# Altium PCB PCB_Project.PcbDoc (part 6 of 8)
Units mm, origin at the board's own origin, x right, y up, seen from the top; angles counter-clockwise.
Board outline 250 x 200 mm, 6 copper layers (Top Shielding/Sig, Sig 1, PWR, GND, Sig 4, Bottom Shielding/Sig), stack 1.568 mm thick; 736 components, 420 nets, 1929 pads, 2185 vias.
Unrouted connection lines stored in the file: 47.
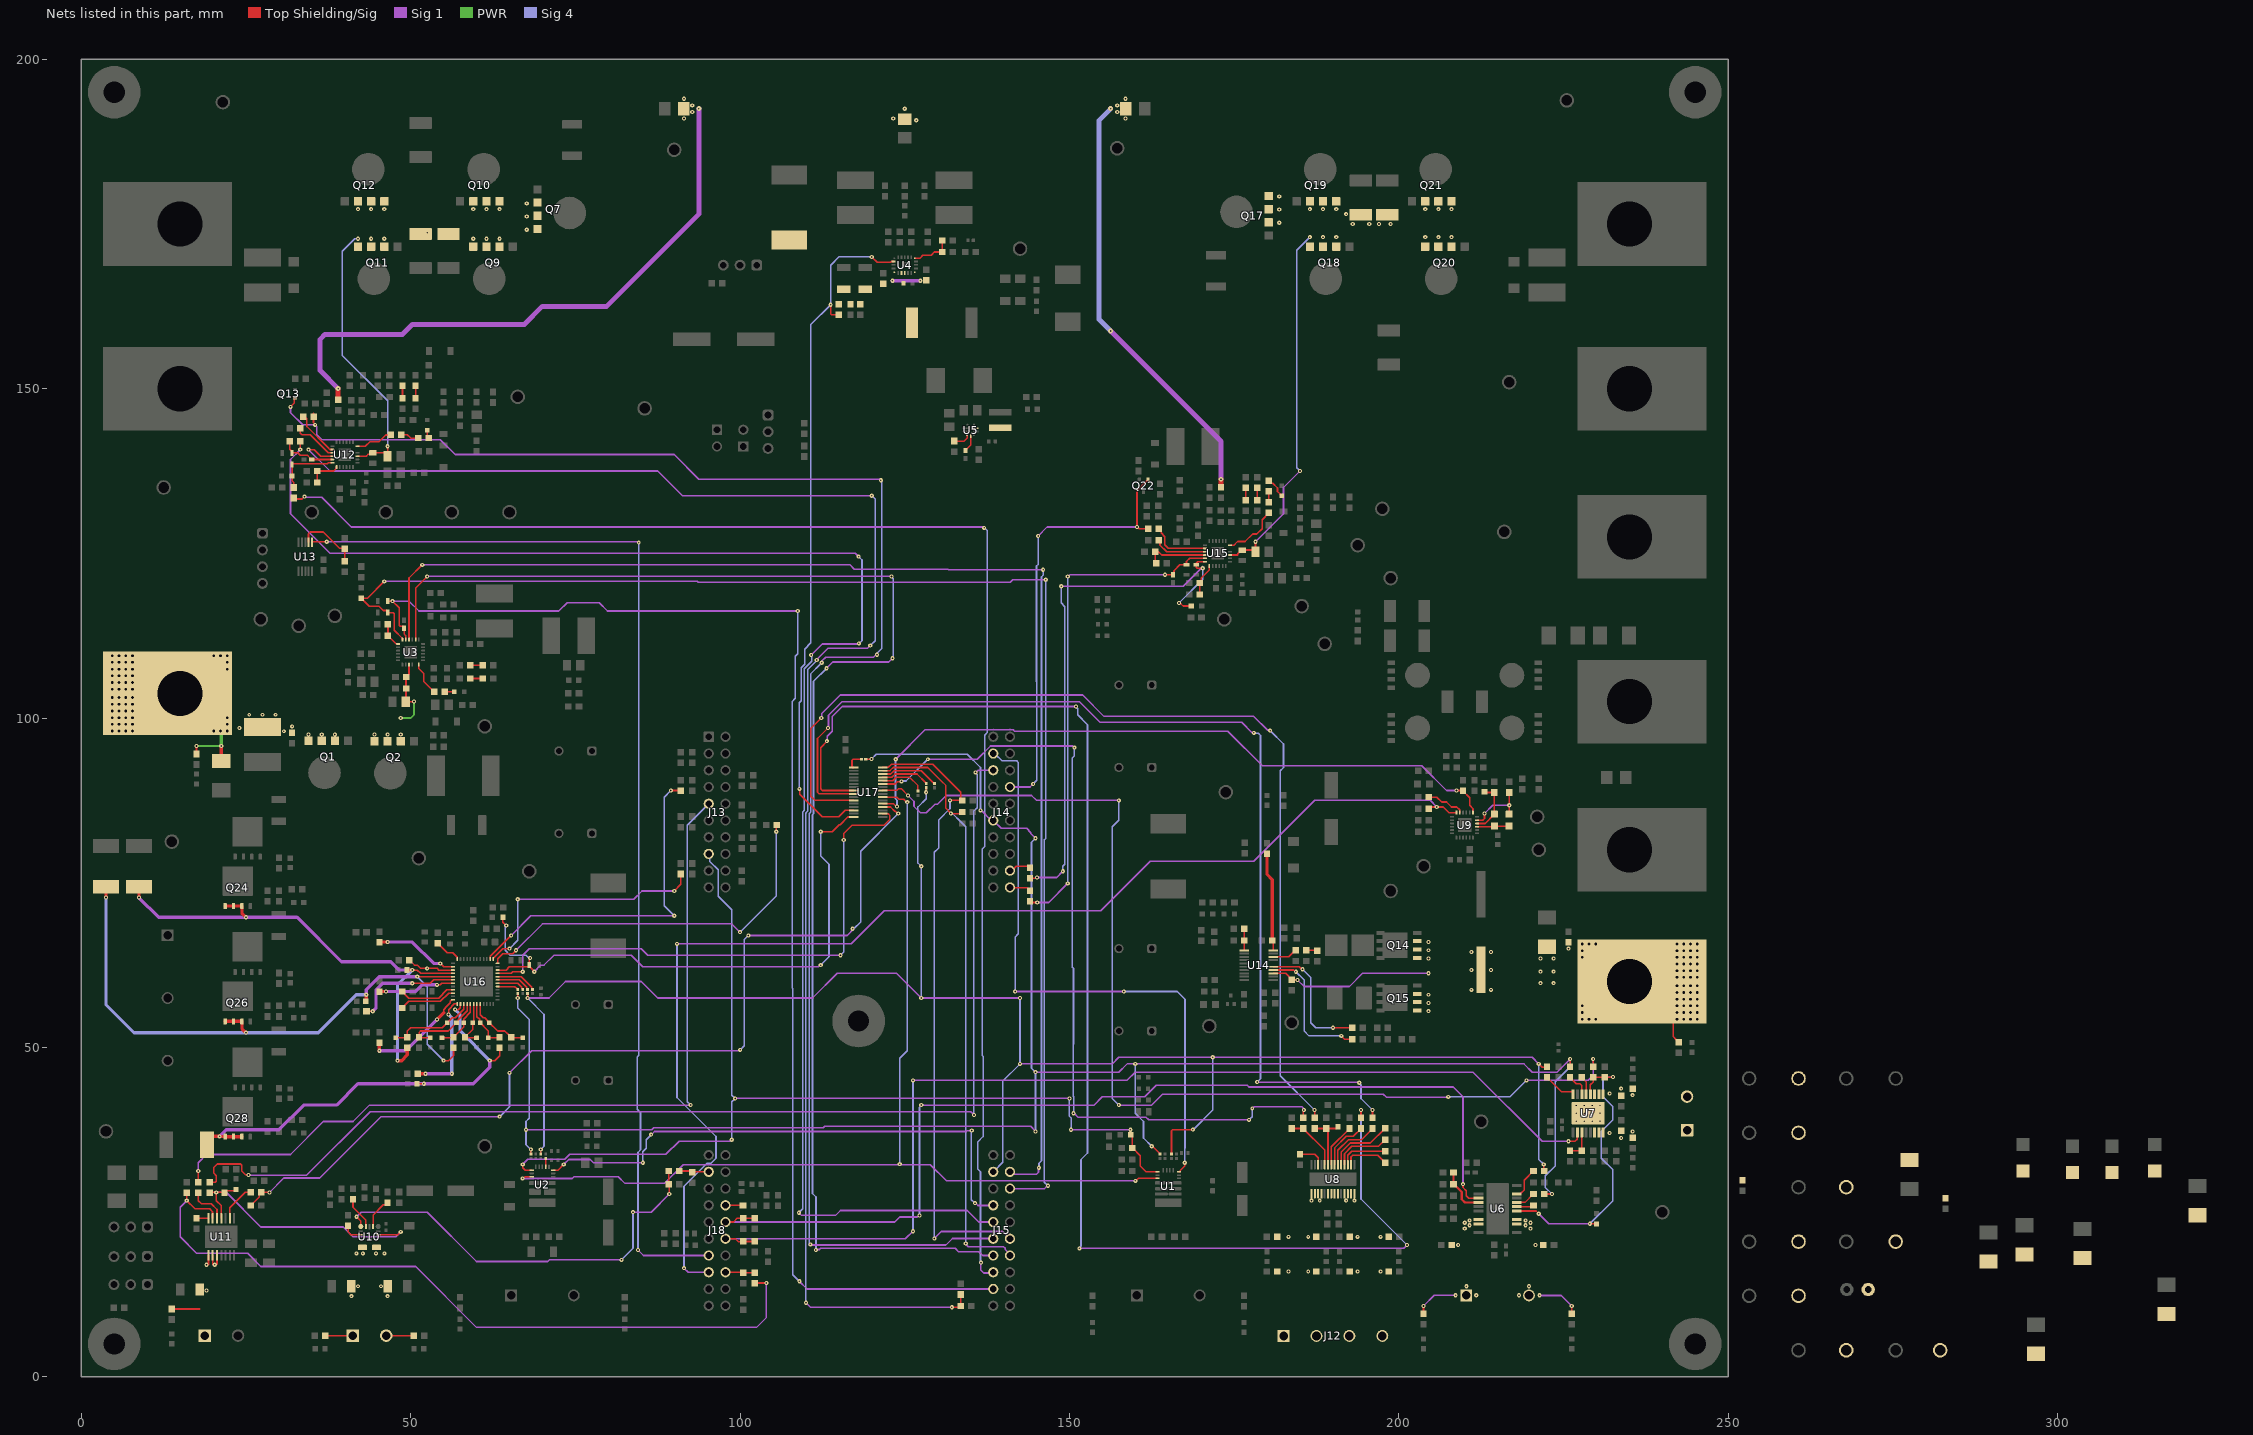
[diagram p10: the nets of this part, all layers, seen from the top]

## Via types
v1: diameter 0.635, hole 0.254, Top Shielding/Sig to Bottom Shielding/Sig, tented both sides, 778 vias
v2: diameter 0.6, hole 0.254, Top Shielding/Sig to Bottom Shielding/Sig, tented both sides, 726 vias
v3: diameter 0.813, hole 0.406, Top Shielding/Sig to Bottom Shielding/Sig, 522 vias
v4: diameter 0.5, hole 0.2, Top Shielding/Sig to Bottom Shielding/Sig, tented both sides, 95 vias
v5: diameter 0.5, hole 0.2, Top Shielding/Sig to Bottom Shielding/Sig, 39 vias
v6: diameter 0.635, hole 0.254, Top Shielding/Sig to Bottom Shielding/Sig, 10 vias
v7: diameter 0.63, hole 0.33, Top Shielding/Sig to Bottom Shielding/Sig, tented both sides, 6 vias
v8: diameter 0.75, hole 0.254, Top Shielding/Sig to Bottom Shielding/Sig, tented both sides, 6 vias
v9: diameter 0.5, hole 0.2, Top Shielding/Sig to Bottom Shielding/Sig, tented top, 3 vias

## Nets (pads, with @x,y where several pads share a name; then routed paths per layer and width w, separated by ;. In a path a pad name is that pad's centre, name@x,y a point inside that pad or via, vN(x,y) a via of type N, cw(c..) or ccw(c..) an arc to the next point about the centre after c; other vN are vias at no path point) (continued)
NetR20_2: R20.2 U2.12 | length 1.3
  Top Shielding/Sig w0.25: U2.12@70.5,31.875 R20.2@70.5,33.17
NetR28_1: R28.1 R31.2 | length 1.9
  Top Shielding/Sig w0.25: R31.2@59.05,108 R28.1@60.95,108
NetR29_1: R29.1 R32.2 | length 1.9
  Top Shielding/Sig w0.25: R32.2@59.05,106 R29.1@60.95,106
NetR37_2: R37.2 RNTC_1.1 | length 1.4
  Top Shielding/Sig w0.25: R37.2@55.175,104 RNTC_1.1@56.6,104
NetR60_2: R60.2 U5.7 | length 2.7
  Top Shielding/Sig w0.25: R60.2@132.5,142.05 132.55,142 134,142 134.463,142.463 U5.7@134.463,142.963
NetR90_1: R90.1 U8.2 | length 6.9
  Top Shielding/Sig w0.25: U8.2@192.75,32.2 192.75,33.375 193,33.625 196.8,33.625 197.925,32.5 R90.1@197.95,32.5
NetR91_1: R91.1 U8.3 | length 7.4
  Top Shielding/Sig w0.25: U8.3@192.25,32.2 192.25,33.625 192.875,34.25 R91.1@197.95,34.25
NetR92_1: R92.1 U8.4 | length 8.8
  Top Shielding/Sig w0.25: U8.4@191.75,32.2 191.75,33.875 192.875,35 196.925,35 197.925,36 R92.1@197.95,36
NetR93_1: R93.1 U8.5 | length 10.1
  Top Shielding/Sig w0.25: U8.5@191.25,32.2 191.25,34.125 192.625,35.5 195.675,35.5 197.925,37.75 R93.1@197.95,37.75
NetR94_1: R94.1 U8.8 | length 6.6
  Top Shielding/Sig w0.25: U8.8@189.75,32.2 189.75,34.925 192.5,37.675 R94.1@192.5,37.7
NetR95_1: R95.1 U8.7 | length 7.8
  Top Shielding/Sig w0.25: U8.7@190.25,32.2 190.25,34.73 192.02,36.5 193.075,36.5 194.25,37.675 R95.1@194.25,37.7
NetR96_1: R96.1 U8.6 | length 8.8
  Top Shielding/Sig w0.25: U8.6@190.75,32.2 190.75,34.375 192.375,36 194.325,36 196,37.675 R96.1@196,37.7
NetR98_1: R98.1 R100.1 U8.10 | length 8.6
  Top Shielding/Sig w0.25: R98.1@183.75,37.7 R100.1@185.5,37.7 185.5,37.675 188.75,34.425 U8.10@188.75,32.2
NetR102_2: R102.2 U8.12 | length 4
  Top Shielding/Sig w0.2: R102.2@185,33.8 185.05,33.75 187.25,33.75 187.75,33.25 U8.12@187.75,32.2
NetR127_2: R127.2 U9.11 | length 5.9
  Top Shielding/Sig w0.25: R127.2@204.55,88 205.75,88 206.5,87.25 207.25,87.25 208,86.5 208.814,86.5 209.241,86.072 209.241,85.878 209.25,85.869 U9.11@209.25,85.65
NetR131_2: R131.2 U10.9 | length 4.5
  Top Shielding/Sig w0.25: R131.2@41.25,26.5 41.25,25.75 43.2,23.8 U10.9@43.2,22.825
NetR132_2: R132.2 U10.7 | length 4.7
  Top Shielding/Sig w0.25: U10.7@44.3,22.825 44.3,24.55 45.847,26.097 46.15,26.097 46.5,26.447 R132.2@46.5,26.45
NetR133_1: R133.1 R135.2 U10.10 | length 63.6
  Top Shielding/Sig w0.25: v1(41.796,24.296) 42.424,23.667 U10.10@42.424,22.825 ; R133.1@89.2,31.25 R135.2@89.2,29.25 89.25,29.2 v1(89.25,27.75)
  Sig 1 w0.25: v1(41.796,24.296) 42.5,25 52.5,25 60,17.5 70.823,17.5 71.073,17.75 v1(82,17.75) ; v1(83.75,25) 86.5,25 v1(89.25,27.75)
  Sig 4 w0.25: v1(82,17.75) 83.75,19.5 v1(83.75,25)
NetR137_2: R137.2 U10.12 | length 3
  Top Shielding/Sig w0.25: R137.2@40.5,22.95 40.5,22 40.925,21.575 U10.12@42.4,21.575
NetR143_2: R143.2 U11.2 | length 5.7
  Top Shielding/Sig w0.25: U11.2@22.55,24.05 22.55,25.654 24.896,28 R143.2@25.7,28
NetR144_2: R144.2 U11.5 | length 6
  Top Shielding/Sig w0.25: R144.2@17.75,27.95 17.75,26.75 18.25,26.25 19.75,26.25 20.6,25.4 U11.5@20.6,24.05
NetR145_2: R145.2 U11.7 | length 1.9
  Top Shielding/Sig w0.25: R145.2@17.5,23.8 17.75,24.05 U11.7@19.3,24.05
NetR156_1: R156.1 R181.2 U12.4 | length 248.3
  Top Shielding/Sig w0.25: v1(34.5,140.75) 35.341,140.75 36.341,139.75 U12.4@38.1,139.75 ; v1(132.155,10.558) 133.125,10.558 133.25,10.683 R181.2@133.25,10.75 ; R181.2@133.5,10.75 R156.1@133.5,12.5
  Sig 1 w0.25: v1(34.5,140.75) 37.75,137.5 87.5,137.5 91.25,133.75 v1(120,133.75) ; v1(110,11.25) 110.692,10.558 v1(132.155,10.558) ; v1@111.639,108.889 113.357,110.608 119.358,110.608 v1(119.75,111)
  Sig 4 w0.25: v1(110,11.25) 109.95,11.3 109.95,85.564 110.25,85.864 110.25,107.335 111.564,108.649 111.564,108.661 v1@111.5,108.725 ; v1(119.75,111) 120.5,111.75 120.5,133.25 v1(120,133.75)
  other v1: 111.645,108.819
NetR163_1: R163.1 R167.2 | length 1.9
  Top Shielding/Sig w0.25: R167.2@50.75,148.55 R163.1@50.75,150.45
NetR164_1: R164.1 R168.2 | length 1.9
  Top Shielding/Sig w0.25: R168.2@48.75,148.55 R164.1@48.75,150.45
NetR176_2: R176.2 U12.3 | length 6.7
  Top Shielding/Sig w0.25: R176.2@33.25,144 33.25,143.25 33.5,143 34.75,143 37.5,140.25 U12.3@38,140.25
NetR178_2: R178.2 U12.2 | length 6.9
  Top Shielding/Sig w0.25: R178.2@33.95,145.75 34.25,145.45 34.25,144.25 37.475,141.025 37.475,141.02 37.735,140.76 U12.2@38.09,140.76
NetR179_1: R179.1 R180.1 | length 2.8
  Top Shielding/Sig w0.25: R179.1@48.55,143 49.5,143 50,142.5 R180.1@51.15,142.5
NetR179_2: R179.2 U12.18 | length 5.8
  Top Shielding/Sig w0.25: U12.18@41.9,141.25 43.114,141.25 43.814,141.95 45.2,141.95 46.221,142.971 46.971,142.971 R179.2@47,143
NetR180_2: R180.2 RNTC_2.1 | length 1.3
  Top Shielding/Sig w0.25: RNTC_2.1@52.5,143.7 52.5,142.75 R180.2@52.75,142.5
NetR196_1: R196.1 R201.1 | length 1.7
  Top Shielding/Sig w0.212: R201.1@185.925,64.75 187.55,64.75 R196.1@187.625,64.675
NetR200_1: R200.1 R203.2 U14.1 | length 3.3
  Top Shielding/Sig w0.25: U14.1@176.55,64.75 R203.2@176.55,66.25 R200.1@176.55,68
NetR201_2: R201.2 U14.18 | length 3.8
  Top Shielding/Sig w0.25: U14.18@180.925,63.725 U14.18@180.95,63.75 183.3,63.75 184.3,64.75 R201.2@184.325,64.75
NetR205_2: R205.2 U14.15 | length 19.9
  Top Shielding/Sig w0.25: U14.15@180.95,62.25 184.896,62.25 185.271,61.875 v1(185.375,61.875) ; v1(190,53) R205.2@192.95,53
  Sig 4 w0.25: v1(185.375,61.875) 186.625,60.625 186.625,53.75 187.375,53 v1(190,53)
NetR206_2: R206.2 U14.14 | length 20.9
  Top Shielding/Sig w0.25: U14.14@180.95,61.75 184.021,61.75 184.271,61.5 v1(184.375,61.5) ; v1(191.25,51.75) 191.75,51.25 R206.2@192.95,51.25
  Sig 4 w0.25: v1(184.375,61.5) 185.625,60.25 185.625,52.5 186.375,51.75 191.125,51.75 v1@191.25,51.625
NetR224_1: R224.1 R228.2 | length 1.9
  Top Shielding/Sig w0.25: R228.2@176.75,133.05 R224.1@176.75,134.95
NetR225_1: R225.1 R229.2 | length 1.9
  Top Shielding/Sig w0.25: R229.2@178.5,133.05 R225.1@178.5,134.95
NetR237_2: R237.2 U15.3 | length 7.9
  Top Shielding/Sig w0.25: R237.2@163.75,127 163.75,126.25 164.75,125.25 U15.3@170.5,125.25
NetR239_2: R239.2 U15.2 | length 9.2
  Top Shielding/Sig w0.2: R239.2@163.5,128.75 163.75,128.5 163.775,128.5 163.9,128.375 163.9,128.1 164.476,127.524 164.476,126.274 165,125.75 U15.2@170.6,125.75
NetR240_1: R240.1 R241.1 | length 1.5
  Top Shielding/Sig w0.25: R240.1@180.25,132.75 R241.1@180.25,134.25 ; R241.1@180.25,134.375 R241.1@180.25,134.4
NetR240_2: R240.2 U15.18 | length 8.6
  Top Shielding/Sig w0.25: U15.18@174.5,126.25 174.973,126.25 175.523,126.8 176.664,126.8 177.814,127.95 178.45,127.95 179.25,128.75 179.25,130.125 180.25,131.125 R240.2@180.25,131.15
NetR241_2: R241.2 RNTC_3.1 | length 3.3
  Top Shielding/Sig w0.25: R241.2@180.25,136 180.25,135.975 180.6,135.625 180.875,135.625 181.575,134.925 181.575,134.4 182.025,133.95 182.025,133.925 182.225,133.725 RNTC_3.1@182.25,133.725
NetR242_2: R242.2 R297.1 U15.4 | length 9.6
  Top Shielding/Sig w0.25: R297.1@163.2,123.5 163,123.7 R242.2@163,125.25 163.5,125.25 164,124.75 U15.4@170.6,124.75
NetR256_2: R256.2 U16.19 | length 5.2
  Top Shielding/Sig w0.2: U16.19@63.212,60.25 66.503,60.25 67.64,59.113 67.64,58.94 R256.2@67.75,58.83
NetR258_2: R258.2 U16.18 | length 4.3
  Top Shielding/Sig w0.2: U16.18@63.212,59.75 66.253,59.75 66.89,59.113 66.89,58.94 R258.2@67,58.83
NetR259_2: R259.2 U16.17 | length 3.2
  Top Shielding/Sig w0.2: U16.17@63.212,59.25 65.83,59.25 66.12,58.96 66.14,58.96 66.25,58.85 R259.2@66.25,58.83
NetR260_2: R260.2 U16.20 | length 6.2
  Top Shielding/Sig w0.2: U16.20@63.212,60.75 66.753,60.75 68.39,59.113 68.39,58.94 R260.2@68.5,58.83
NetR263_1: R263.1 U16.36 | length 4.1
  Top Shielding/Sig w0.2: R263.1@54.125,65.825 54.125,65.8 54.5,65.425 54.525,65.425 55.575,64.375 56.375,64.375 57.042,63.708 57.042,63.42 U16.36@57.062,63.4
NetR264_2: R264.2 U16.38 | length 12.7
  Top Shielding/Sig w0.2: v1(54.5,62.75) 55,62.25 U16.38@56.412,62.25
  Top Shielding/Sig w0.25: R264.2@45.25,65.95 R264.2@45.3,66
  Top Shielding/Sig w0.5: R264.2@45.3,66 v1(46.5,66)
  Sig 1 w0.5: v1(46.5,66) 50.25,66 53.5,62.75 v1(54.5,62.75)
NetR268_2: R268.2 U16.39 | length 7.2
  Top Shielding/Sig w0.2: v1(52.5,62) 54,62 54.25,61.75 U16.39@56.412,61.75
  Top Shielding/Sig w0.25: R268.2@49.8,63.25 49.825,63.25 50.575,62.5 51,62.5 51.5,62 v1(52.5,62)
NetR269_1: R269.1 U16.45 | length 8.7
  Top Shielding/Sig w0.2: R269.1@48.7,58.5 48.725,58.5 49.1,58.125 49.1,58.1 49.7,57.5 54.25,57.5 55.5,58.75 U16.45@56.412,58.75
NetR271_2: R271.2 U16.43 | length 11.7
  Top Shielding/Sig w0.2: v1(54,59.5) 54.013,59.487 54.487,59.487 54.75,59.75 U16.43@56.412,59.75
  Top Shielding/Sig w0.5: R271.2@45.25,58.45 45.3,58.5 v1(46.25,58.5)
  Sig 1 w0.5: v1(46.25,58.5) 50.75,58.5 51.75,59.5 v1(54,59.5)
NetR272_2: R272.2 U16.42 | length 16.7
  Top Shielding/Sig w0.2: v1(50.25,59.75) 53,59.75 53.5,60.25 U16.42@56.412,60.25
  Top Shielding/Sig w0.25: R272.2@43.3,55.5 v1(44.25,55.5)
  Sig 1 w0.5: v1(44.25,55.5) 44.75,56 44.75,58.75 45.75,59.75 v1(50.25,59.75)
NetR274_1: R274.1 U16.46 | length 8.7
  Top Shielding/Sig w0.2: R274.1@48.7,56 48.725,56 49.1,56.375 49.1,56.4 49.7,57 54.5,57 55.75,58.25 U16.46@56.412,58.25
NetR275_2: R275.2 U16.48 | length 16
  Top Shielding/Sig w0.2: 55,55.25 55,55.75 55.5,56.25 56,56.75 56,57.018 56.232,57.25 U16.48@56.412,57.25
  Top Shielding/Sig w0.5: v1(45.25,49.5) R275.2@45.25,50.7 ; v1(54,54.25) 55,55.25
  Sig 1 w0.5: v1(45.25,49.5) 49.25,49.5 v1(54,54.25)
NetR276_2: R276.2 U16.1 | length 16.8
  Top Shielding/Sig w0.2: v1(55.75,55) 55.75,55.75 56.6,56.6 U16.1@57.062,56.6
  Top Shielding/Sig w0.5: R276.2@51.05,46 v1(52.25,46)
  Sig 1 w0.5: v1(52.25,46) v1(56.25,46)
  Sig 4 w0.5: v1(55.75,55) 56.25,54.5 v1(56.25,46)
NetR278_2: R278.2 U16.26 | length 52.5
  Top Shielding/Sig w0.2: U16.26@62.062,63.4 U16.26@62.062,63.4 62.063,63.813 v1(65.25,67)
  Top Shielding/Sig w0.25: v1(89.5,89) 90.95,89 R278.2@91,88.95
  Sig 1 w0.25: v1(65.25,67) 68.25,70 v1(90,70)
  Sig 4 w0.25: v1(89.5,89) 88.5,88 88.5,71.5 v1(90,70)
NetR279_2: R279.2 U16.25 | length 38.5
  Top Shielding/Sig w0.2: U16.25@62.562,63.4 62.562,63.58 62.582,63.6 62.6,63.6 64,65 v1(65,65)
  Top Shielding/Sig w0.25: v1(90,73.75) 91,74.75 R279.2@91,76.325
  Sig 1 w0.25: v1(66.25,72.5) 83.875,72.5 85.125,73.75 v1(90,73.75)
  Sig 4 w0.25: v1(65,65) 66.25,66.25 v1(66.25,72.5)
NetR280_2: R280.2 U16.24 | length 58.8
  Top Shielding/Sig w0.2: U16.24@63.212,62.75 63.212,63.462 64,64.25 65.5,64.25 v1(66,64.75)
  Top Shielding/Sig w0.25: v1(105.5,82.75) 105.5,83.7 R280.2@105.55,83.75
  Sig 1 w0.25: v1(66,64.75) 70,68.75 98.75,68.75 v1(100,67.5)
  Sig 4 w0.25: v1(100,67.5) 105.5,73 v1(105.5,82.75)
NetR293_2: R293.2 U17.29 | length 7.4
  Top Shielding/Sig w0.25: U17.29@121.65,91 121.675,91.025 123.048,91.025 123.523,91.5 126.85,91.5 128.165,90.185 R293.2@128.259,90.091
NetR294_2: R294.2 U17.30 | length 8.9
  Top Shielding/Sig w0.25: U17.30@121.65,91.5 122.886,91.5 123.386,92 127.5,92 129.315,90.185 129.415,90.185 R294.2@129.517,90.083
NetR295_2: R295.2 U17.1 | length 2.8
  Top Shielding/Sig w0.25: U17.1@117.25,92.5 117.025,92.5 117,92.525 117,93.604 117.146,93.75 R295.2@118.42,93.75
NetR296_2: R296.2 U17.28 | length 6.9
  Top Shielding/Sig w0.25: U17.28@121.65,90.5 123.159,90.5 123.694,91.035 125.715,91.035 127,89.75 R296.2@127,89
NetR302_1: R302.1 R303.2 U13.2 | length 9.9
  Top Shielding/Sig w0.25: U13.2@34.5,126.7 34.5,128 34.75,128.25 36.75,128.25 39.25,125.75 40,125.75 R302.1@40,125.7 R303.2@40,123.8
NetR306_2: R306.2 TP44.1 U7.17
  other v4: 226.95,38.8 228.15,38.8 230.55,38.8 226.95,40 228.15,40 230.55,40 226.95,41.2 228.15,41.2 230.55,41.2
  other v9: 229.35,38.8 229.35,40 229.35,41.2
NetR307_2: R307.2 TP46.1 U8.20 U8.21 U8.22 U8.23
nFAULT_48V_efuse_1: J14.38 R147.1 | length 179.5
  Top Shielding/Sig w0.25: R147.1@19.5,29.55 20.35,29.55 20.496,29.696 20.496,30.537 20.108,30.926 20.108,31.766 20.641,32.3 24.185,32.3 24.375,32.11 24.375,31.234 24.91,30.699 25.298,30.699 v1(25.372,30.625)
  Sig 1 w0.25: v1(25.372,30.625) 34.239,30.625 43.864,40.25 135,40.25 v1(135.5,39.75) ; v2(135.75,91.75) 135.845,91.75 136.17,92.075 138.325,92.075 J14.38@138.415,92.165
  Sig 4 w0.25: v1(135.5,39.75) 135.5,85.884 136,86.384 136,91.429 135.75,91.679 v2(135.75,91.75)
nFAULT_48V_efuse_5: D28.1 R146.1 R147.2 U10.4 U11.4 | length 43.2
  Top Shielding/Sig w0.25: R147.2@19.5,27.95 19.7,27.95 19.75,28 v1(20.5,28) ; U11.4@21.25,24.05 21.25,26 20.5,26.75 v1(20.5,28) ; D28.1@23.5,28.45 23.3,28.25 22.05,28.25 R146.1@21.75,27.95 21.7,28 v1(20.5,28) ; U10.4@45.1,21.575 48.075,21.575 v1(48.5,22)
  Sig 1 w0.25: v1(20.5,28) 22,28 27.25,22.75 39.75,22.75 41.25,21.25 47.75,21.25 v1(48.5,22)
nFAULT_1212_1_2: D37.1 R184.1 R185.1 U12.6 | length 9.7
  Top Shielding/Sig w0.25: R185.1@32.25,135 32.25,135.75 32,136 D37.1@32,136.75 R184.1@32,138.5 32.125,138.625 37.375,138.625 37.5,138.75 U12.6@38,138.75
nFAULT_1212_2_3: D46.1 R245.1 R246.1 U15.6 | length 83.9
  Top Shielding/Sig w0.2: R245.1@169.25,123.25 169.25,122.867 169.367,122.75 v1(170.25,122.75)
  Top Shielding/Sig w0.25: R246.1@144,75.7 v1@144.95,75.7 ; v2@166.75,117.5 167.25,117 D46.1@168.5,117 ; R245.1@169.25,123.25 169.25,123.5 169.5,123.75 U15.6@170.6,123.75
  Sig 1 w0.2: v1(148.75,120) 167.25,120 v1@170.25,123
  Sig 1 w0.25: v1@145,75.75 145.051,75.801 v1(145.076,75.801) 148.051,75.801 v1(149,76.75)
  Sig 4 w0.2: v1(148.75,120) 148.75,117.5 149.325,116.925 149.325,77.803 149,77.478 v1(149,76.75)
  Sig 4 w0.25: v2(166.643,117.464) 170.25,121.07 v1(170.25,122.75) v1@170.25,123
nFAULT_1214: D9.1 J15.58 R40.1 U3.6 | length 214.1
  Top Shielding/Sig w0.25: v1(46,120.75) 43.45,118.2 D9.1@42.5,118.2 43.725,116.975 45.185,116.975 45.835,116.325 46.375,116.325 46.5,116.2 R40.1@46.5,116 47.354,116 47.5,115.854 47.5,113.325 48.75,112.075 U3.6@48.75,111.9
  Sig 1 w0.25: v1(46,120.75) 93.489,120.75 93.631,120.607 141.016,120.607 141.409,121 v1(146.393,121) ; J15.58@141,28.75 141.175,28.575 146.221,28.575 146.646,29 v1(146.75,29)
  Sig 4 w0.25: J15.58@141,28.5 J15.58@141.072,28.572 ; v1(146.393,121) 146.393,81.709 146.2,81.516 146.2,29.55 v1(146.75,29)
nFAULT_DRV82xx_1: D3.1 J13.8 R4.1 U1.1 U2.1 | length 154.3
  Top Shielding/Sig w0.2: v1(67,32.25) 67,31.75 67.375,31.375 U2.1@68.375,31.375
  Top Shielding/Sig w0.25: v1(159.25,37.5) 159.25,36.8 D3.1@159.3,36.75 159.55,36.5 R4.1@159.55,34.75 159.575,34.75 160.75,33.575 160.75,32 161.625,31.125 U1.1@163.375,31.125
  Sig 1 w0.2: v1(67,32.25) 67.75,33 73.399,33 74.149,33.75 88.75,33.75 90.75,35.75 98.415,35.75 98.665,36 v1(98.75,36) ; v1(99.25,42.25) v1(150,42.25) ; v1(150.25,37.5) v1(159.25,37.5)
  Sig 4 w0.25: J13.8@95.25,79.375 95.416,79.209 95.416,78.225 96.69,76.951 96.69,72.944 98.75,70.884 98.75,42.75 v1(99.25,42.25) 98.75,41.75 v1(98.75,36) ; v1(150,42.25) 149.965,42.215 149.965,39.586 150.25,39.301 v1(150.25,37.5)
nFAULT_DRV8363: D50.1 R262.1 U16.22 U17.16 | length 89.3
  Top Shielding/Sig w0.2: U16.22@63.212,61.75 64.5,61.75 65,62.25 67.85,62.25 R262.1@67.95,62.35 ; R262.1@68,62.5 68,62.3 68.75,61.55 v1(68.75,61.5)
  Top Shielding/Sig w0.25: D50.1@64,69.75 64,69 v1(64.5,68.5) ; R262.1@68,62.5 v1@68,63.5 ; v1(112.25,82.75) 113.99,82.75 115.04,83.8 115.186,83.8 116.361,84.975 117.225,84.975 U17.16@117.25,85
  Sig 1 w0.25: v1(68.75,61.5) 69.75,62.5 70.25,62.5 71.75,64 83.5,64 85.25,62.25 111.911,62.25 112.161,62.5 v1(112.25,62.5)
  Sig 4 w0.25: v1(64.5,68.5) 64.5,68.396 64.357,68.253 64.357,64.734 65.091,64 67.521,64 v1@68,63.521 ; v1(112.25,62.5) 113.5,63.75 113.5,77.823 112.25,79.073 v1(112.25,82.75)
  other v1: 68.13,63.568
nFAULT_LM74900_1: J18.48 R125.1 U9.12 | length 187.4
  Top Shielding/Sig w0.25: R125.1@204.55,86.25 204.8,86.5 v1(205.75,86.5) 206.75,86.5 207.6,85.65 U9.12@208.75,85.65
  Sig 1 w0.25: v2@90.5,65.75 116.866,65.75 121.866,70.75 154.75,70.75 162.25,78.25 178,78.25 187.25,87.5 204.75,87.5 v1(205.75,86.5) ; v2(91.5,16.5) 92.125,15.875 95.125,15.875 J18.48@95.25,15.75
  Sig 4 w0.25: v2(90.437,65.726) 90.437,42.404 96.35,36.491 96.35,33.199 95.536,32.385 94.964,32.385 91.5,28.921 v2(91.5,16.5)
nFAULT_TPS4HC120_1: R99.2 U17.11 | length 153.4
  Top Shielding/Sig w0.25: v1(112.339,100) 110.75,98.411 110.75,88.114 111.364,87.5 U17.11@117.25,87.5 ; R99.2@187.25,39.3 v1@187.25,40.5
  Sig 1 w0.25: v1(112.339,100) 112.412,100.074 112.412,100.685 115.227,103.5 152,103.5 155.25,100.25 178,100.25 180.094,98.156 180.401,98.156 v2(180.468,98.089)
  Sig 4 w0.25: v2@180.5,98 180.557,98 182.5,96.057 182.5,92.5 182,92 182,45.705 v1(187.2,40.505)
nFLT_LM686x5_1: R49.1 U4.8 U17.14 | length 105.6
  Top Shielding/Sig w0.25: v1(109,89.25) 109.074,89.176 109.074,88.426 112.5,85 114.967,85 115.967,86 U17.14@117.25,86 ; v6(113.75,162.75) 113.75,161.346 113.896,161.2 R49.1@115,161.2 R49.1@115.05,161.25 ; v1(120,170) 120.832,169.168 122.813,169.168 122.945,169.3 U4.8@123.3,169.3
  Sig 4 w0.25: v1(109,89.25) 109,102.321 109.3,102.621 109.3,107.658 109.8,108.158 109.8,110.465 110.75,111.415 110.75,159.75 v6(113.75,162.75) 113.75,168.75 115,170 v1(120,170)
nFLT_TPS2HCS10/05_1: R84.1 U17.25 | length 164.3
  Top Shielding/Sig w0.25: U17.25@121.65,89 121.675,89.025 122.344,89.025 123.836,89.025 124.061,89.25 124.5,89.25 v1(125.5,88.25) ; R84.1@229.5,47.05 v1(229.5,48.25)
  Sig 1 w0.25: v1(125.5,88.25) 126.412,87.338 126.412,86.588 127.393,85.607 128.266,85.607 129.587,86.929 129.974,86.929 131.295,88.25 144.25,88.25 145,87.5 v1(157.5,87.5) ; v1(157.5,41.25) 162.5,41.25 164.125,42.875 180.876,42.875 180.893,42.892 197.644,42.892 198.071,42.465 207.465,42.465 v1(207.5,42.5) ; v1(219.375,45) 228.75,45 229.5,45.75 v1(229.5,48.25)
  Sig 4 w0.25: v1(157.5,41.25) 156.573,42.177 156.5,42.25 156.5,52.275 cw(c157.5,52.5) 156.5,52.725 156.5,64.775 cw(c157.5,65) 156.5,65.225 156.5,83.5 157.5,84.5 v1(157.5,87.5) ; v1(207.5,42.5) 216.875,42.5 v1(219.375,45)
nFLT_TPS2HCS10/05_4: D14.1 R82.1 R84.2 U6.13 U7.12 | length 45.6
  Top Shielding/Sig w0.25: U6.13@217.9,25.175 220.825,25.175 v1(221.25,24.75) ; v1(229,23.25) 229.95,23.25 D14.1@230,23.2 ; U7.12@229.075,42.9 229.075,44.325 229.5,44.75 R84.2@229.5,45.45 R82.1@231.25,45.45 231.3,45.5 v1(232.5,45.5)
  Sig 1 w0.25: v1(221.25,24.75) 222.75,23.25 v1(229,23.25)
  Sig 4 w0.25: v1(229,23.25) 232.5,26.75 232.5,31.45 230.75,33.2 230.75,37.25 232.5,39 232.5,41 231,42.5 231,45 231.5,45.5 v1(232.5,45.5)
nFLT_TPS4HC120_9: D19.1 R97.1 R99.1 U8.9 | length 9.2
  Top Shielding/Sig w0.25: R99.1@187.25,37.7 R97.1@189,37.7 ; U8.9@189.25,32.2 189.25,37.45 R97.1@189,37.7 ; D19.1@190.75,37.95 190.5,37.7 R97.1@189,37.7
nFLT_TPS1212_input1_1: J15.73 R185.2 | length 222.6
  Top Shielding/Sig w0.25: R185.2@32.25,133.5 32.5,133.25 33.5,133.25 33.858,133.608 v2(33.895,133.608)
  Sig 1 w0.25: v2@34,133.5 36.5,133.5 41,129 v2@137,129 ; v2@136.54,17.114 136.54,16.21 137,15.75 J15.73@138.5,15.75
  Sig 4 w0.25: v2@136.5,17.25 136.5,31.119 136.108,31.511 136.108,35.699 136.892,36.484 136.892,48.671 136.75,48.813 136.75,80.125 137.125,80.5 137.125,97.406 137.5,97.781 137.5,128.5 v2@137,129
  other v2: 136.569,17.322 137.051,128.878
nFLT_TPS1212_input2_1: J14.12 R246.2 | length 3.2
  Top Shielding/Sig w0.25: J14.12@140.97,76.835 141.266,76.835 141.931,77.5 R246.2@143.75,77.5 ; J14.12@141,76.75 J14.12@141.027,76.777 ; R246.2@144,77.3 R246.2@144.085,77.385
nINT_TXE8124_1: J15.55 R290.2 U17.32 | length 96.8
  Top Shielding/Sig w0.25: U17.32@121.65,92.5 121.663,92.513 122.513,92.513 123,93 129.25,93 133.5,88.75 R290.2@133.5,87.5 ; v2(131.875,87.5) R290.2@133.5,87.5 ; R290.2@133.7,87.5 R290.2@133.5,87.5
  Sig 1 w0.25: v1(129.5,21) 130.555,22.055 139.87,22.055 140.925,21 J15.55@141,21
  Sig 4 w0.25: v1(129.5,21) 129.5,79.636 130.143,80.279 130.143,84.526 131.875,86.259 v2(131.875,87.5)
nLPM_TPS4HC120_1: R100.2 U17.27 | length 125.5
  Top Shielding/Sig w0.25: U17.27@121.65,90 123.538,90 123.857,90.319 124.426,90.319 v1(124.5,90.393) ; R100.2@185.5,39.3 v1@185.5,40.5
  Sig 1 w0.25: v2(128.5,93.75) 136.009,93.75 138.009,95.75 150.5,95.75 v2(150.75,95.5) ; v1(150.607,40) 150.712,40 151.312,39.4 161.623,39.4 162.023,39 v2(177.25,39) ; v2(177.75,40.75) 177.835,40.75 178.071,40.987 185.297,40.987 185.513,40.77 185.513,40.578 v1(185.587,40.504)
  Sig 4 w0.25: v1(124.5,90.393) 124.55,90.442 125.192,90.442 v2(128.5,93.75) ; v1(150.607,40) 150.643,40.035 150.643,42.516 150.57,42.589 150.57,50.446 150.607,50.484 150.607,62.006 150.45,62.164 150.45,93.95 150.75,94.25 v2@150.75,95.25 ; v2(177.25,39) 177.75,39.5 v2(177.75,40.75)
nLPM_TPS1212_input1_1: J15.75 Q13.1 R178.1 | length 252.1
  Top Shielding/Sig w0.25: v2(31.75,147.25) 32.354,147.854 32.354,148.49 32.364,148.5 Q13.1@32.5,148.5 ; 35.25,146.25 35.25,144.854 35.5,144.604 v1(35.5,144.5)
  Sig 1 w0.25: v2(31.75,147.25) 31.75,146.366 33.616,144.5 v1(35.5,144.5) 35.75,144.25 35.75,143 36.5,142.25 54.5,142.25 56.75,140 90,140 93.75,136.25 v1@121.25,136.25 ; v2@110.544,20 131.25,20 132.25,21 J15.75@138.25,21 ; v1@112.253,108.247 112.327,108.321 112.327,108.577 113,109.25 120.25,109.25 120.635,109.635 v1@120.635,109.683
  Sig 4 w0.25: v2@110.5,20 110.5,20.118 110.5,85.477 110.708,85.685 110.708,106.701 v1@112.253,108.247 ; v1@120.635,109.683 121.5,110.548 121.5,135.911 121.25,136.161 v1@121.25,136.25
  other v1: 112.388,108.391 120.779,109.61 121.372,136.099
  other v2: 110.661,20.118
nLPM_TPS1212_input2_1: J14.17 Q22.1 R239.1 | length 66.5
  Top Shielding/Sig w0.25: Q22.1@161.75,136 160.25,134.5 v1(160.25,129) 160.354,129 160.604,128.75 R239.1@161.95,128.75
  Sig 1 w0.25: J14.17@140.97,89.535 144.01,89.535 144.475,90 v2(144.5,90) ; v1(145.25,127.643) 146.607,129 v1(160.25,129)
  Sig 4 w0.25: v2@144.666,90.166 145.05,90.55 145.05,105.471 145,105.521 145,123.073 145.25,123.323 v1(145.25,127.643)
nLPM_TPS1214_1: J15.74 U3.2 | length 220.7
  Top Shielding/Sig w0.25: U3.2@50.75,111.9 50.75,119.75 v1(52.5,121.5)
  Sig 1 w0.25: v1(52.5,121.5) v1(123,121.5) ; v2(111.5,19.25) 111.567,19.317 112.067,19.317 112.25,19.5 132.659,19.5 133.159,19 136.25,19 136.835,18.415 J15.74@138.43,18.415 ; v1@113.25,107.5 113.25,107.674 114.076,108.5 122.576,108.5 v1(123.145,109.069)
  Sig 4 w0.25: v2(111.5,19.25) 111.53,19.28 111.53,27.299 111,27.829 111,85.341 111.157,85.498 111.157,105.582 v1(113.145,107.569) ; v1(123,121.5) 123,121.411 123.25,121.161 v1@123.25,109.25
nSLEEP_DRV82xx_1: U1.3 U2.3 U17.23 | length 159.8
  Top Shielding/Sig w0.25: v2@67.25,30.25 67.375,30.375 U2.3@68.375,30.375 ; U17.23@121.65,88 123.795,88 124.123,87.672 124.848,87.672 125.25,87.27 v1@125.25,87.25 ; v2(160,29.75) 160.095,29.75 160.47,30.125 U1.3@163.375,30.125
  Sig 1 w0.25: v2(67,30.125) 67.018,30.107 74.516,30.107 74.801,30.392 81.491,30.392 82.526,29.358 88.5,29.358 91.357,32.215 128.875,32.215 131.34,29.75 v2(160,29.75)
  Sig 4 w0.25: v1@124.25,32.25 124.25,48.341 125.385,49.476 v1(125.385,87.239)
  other v1: 124.234,32.283
nSLEEP_DRV8363_1: U16.21 U17.18 | length 83.9
  Top Shielding/Sig w0.2: U16.21@63.212,61.25 65.25,61.25 65.5,61.5 v1(67,61.5)
  Top Shielding/Sig w0.25: v1(115.75,81.5) 115.766,81.516 115.766,82.516 117,83.75 121.864,83.75 122.75,84.636 122.75,85.206 122.481,85.475 121.675,85.475 U17.18@121.65,85.5
  Sig 1 w0.25: v1(67,61.5) 67,64 68,65 85,65 86,64 v1(115.25,64)
  Sig 4 w0.25: v1(115.25,64) 115.75,64.5 v1(115.75,81.5)
nSLEEP_LM74900_1: R124.1 U9.7 U17.21 | length 105.3
  Top Shielding/Sig w0.25: U17.21@121.65,87 123.304,87 123.725,86.579 v1(123.829,86.579) ; v1(208.75,89) R124.1@209.675,89 ; R124.1@209.75,88.95 209.75,88.925 210.75,87.925 210.75,86.75 211.25,86.25 U9.7@211.25,85.65
  Sig 1 w0.25: v1(123.625,93.744) 128.131,98.25 138.325,98.25 cw(c138.43,97.155) 138.535,98.25 140.865,98.25 cw(c140.97,97.155) 141.075,98.25 141.431,98.25 141.504,98.177 141.681,98 174.05,98 179.3,92.75 203.5,92.75 207.25,89 v1(208.75,89)
  Sig 4 w0.25: v1(123.625,93.744) 123.607,93.727 123.607,87.756 123.829,87.535 v1(123.829,86.579)
OUT1_TPS4HC120: C86.1 D55.1 J12.4 R105.2 U8.27 U8.28
  other v2: 197.25,16 197.25,21.25 193.25,26.75
OUT2_TPS4HC120: C89.1 D56.1 J12.3 R106.2 U8.25 U8.26
  other v2: 193.75,16 193.75,21.25 192,26.75
OUT3_TPS4HC120: C90.1 D57.1 J12.2 R107.2 U8.17 U8.18
  other v2: 186.25,16 186.25,21.25 188,26.75
OUT4_TPS4HC120: C91.1 D58.1 J12.1 R108.2 U8.15 U8.16
  other v2: 183.25,16 183.25,21.25 186.75,26.75
OV_11: R121.2 R122.2 U9.5 | length 9.5
  Top Shielding/Sig w0.25: U9.5@211.9,84.5 212.75,84.5 213,84.75 v1(213,85.5) ; R122.2@216.75,85.401 R121.2@216.75,88.7
  Sig 1 w0.25: v1(213,85.5) 214.25,86.75 v1(216.75,86.75)
PH/IN2_DRV8245_1: J14.39 U1.12 | length 92.2
  Top Shielding/Sig w0.25: U1.12@166.625,31.125 166.825,31.125 166.825,31.325 167.5,32 v1(167.5,32.5)
  Sig 1 w0.25: v1(141.75,58.5) v2(158.25,58.5)
  Sig 4 w0.25: J14.39@138.5,94.5 138.75,94.5 139.75,93.5 142,93.5 142.25,93.25 142.25,67.25 141.75,66.75 v1(141.75,58.5) ; v2(158.25,58.5) 166.364,58.5 167.55,57.314 167.55,34.734 167.5,34.684 v1(167.5,32.5)
PH/IN2_DRV8263_1: J15.77 U2.10 | length 82
  Top Shielding/Sig w0.25: U2.10@71.625,31.375 72.375,31.375 v1(73.25,32.25)
  Sig 1 w0.25: v1(73.25,32.25) 74,33 77.25,33 77.75,32.5 v1(85.25,32.5) ; v2(86.5,36.75) 87,37.25 134.357,37.25 134.482,37.375 135.157,37.375 v1(135.175,37.393) ; v1(135.656,26.37) 135.76,26.37 136.13,26 J15.77@138.25,26
  Sig 4 w0.25: v1(85.25,32.5) 85.25,34.177 85.75,34.677 85.75,36 v2(86.5,36.75) ; v1(135.175,37.393) 135.107,37.325 135.107,26.893 v1@135.5,26.5
RESET_TXE8124_1: J15.54 R292.2 U17.31 | length 91.4
  Top Shielding/Sig w0.25: U17.31@121.65,92 121.675,92.025 122.775,92.025 123.25,92.5 128.5,92.5 130.5,90.5 131.25,89.75 131.25,86.321 132,85.571 v2(132,85.5) 133.325,85.5 133.5,85.675 R292.2@133.5,85.75
  Sig 1 w0.25: v6(134.25,20.25) 134.25,20.146 134.646,19.75 140,19.75 140.25,19.5 140.25,19.321 141,18.571 J15.54@141,18.25
  Sig 4 w0.25: v2(132,85.5) 132.067,85.433 132.317,85.433 133.408,84.342 134.25,83.5 v6(134.25,20.25)
SCLK_1: J15.79 R10.1 R13.1 R65.1 R83.1 R256.1 R293.1 | length 282.8
  Top Shielding/Sig w0.25: v1(67.75,57.5) R256.1@67.75,58.17 ; R13.1@69.75,33.83 v1(69.75,34.5) ; v1(128.25,88.75) R293.1@128.25,89.42 ; R10.1@165.5,33.83 165.5,37.354 165.672,37.526 v2(168.741,37.526) ; v1(221.25,47.5) 221.75,47 222.45,47 R83.1@222.5,47.05 ; v1(222,32.25) 222,31.3 R65.1@222.05,31.25
  Sig 1 w0.25: v1(67.75,57.5) 71,57.5 73.5,60 85,60 87.5,57.5 111,57.5 114.75,61.25 123.75,61.25 v1(127.5,57.5) v1(142.5,57.5) ; v1(142.5,47.5) 156.5,47.5 157.5,48.5 v1(171.75,48.5) 220.25,48.5 v1(221.25,47.5)
  Sig 4 w0.25: v1(67.75,57.5) 70.25,55 70.25,35 v1(69.75,34.5) ; v1(127.5,57.5) v1(127.5,77.5) 127,78 127,86.5 128.25,87.75 v1(128.25,88.75) ; J15.79@138.5,31.25 138.565,31.25 139.87,32.555 139.87,38.712 139.893,38.735 139.893,44.893 v1(142.5,47.5) v1(142.5,57.5) ; v2(168.741,37.526) 168.776,37.526 171.75,40.5 v1(171.75,48.5) ; v1(221.25,47.5) 221.25,33 v1(222,32.25)
SCLK_HCS05_4: R65.2 U6.17 | length 4.9
  Top Shielding/Sig w0.25: U6.17@217.9,27.775 218.425,27.775 219.016,28.366 219.016,29.841 220.425,31.25 R65.2@220.45,31.25
SCLK_HCS10_4: R83.2 U7.16 | length 5.2
  Top Shielding/Sig w0.25: R83.2@222.5,45.45 222.5,45.425 222.85,45.075 222.875,45.075 224.7,43.25 226.375,43.25 226.475,43.15 U7.16@226.475,42.9
SCP_TEST_TPS1214_1: J15.59 U3.4 | length 203.1
  Top Shielding/Sig w0.25: U3.4@49.75,111.9 49.75,121.25 v1(51.75,123.25)
  Sig 1 w0.25: v1(51.75,123.25) 116.679,123.25 117.337,122.593 131.57,122.593 131.663,122.5 v1(146,122.5) ; J15.59@140.97,31.115 141.322,31.115 141.687,30.75 145,30.75 145.308,31.058 145.308,31.7 v1(145.357,31.75)
  Sig 4 w0.25: v1(145.357,31.75) 145.375,31.767 145.375,32.442 145.75,32.818 145.75,121.409 146,121.659 v1(146,122.5)
SDI_HCS05_4: R67.2 U6.14 | length 2.6
  Top Shielding/Sig w0.25: U6.14@217.9,25.825 220.275,25.825 R67.2@220.45,26
SDI_HCS10_4: R86.2 U7.13 | length 2.8
  Top Shielding/Sig w0.25: R86.2@227.75,45.45 227.75,45.425 228.425,44.75 U7.13@228.425,42.9
SDO_1: J14.35 R11.1 R19.1 R68.1 R87.1 R259.1 R295.1 | length 306.8
  Top Shielding/Sig w0.25: v1(66.25,57.5) R259.1@66.25,58.17 ; R19.1@68.25,33.83 v1(68.25,34.5) ; R295.1@119.08,93.75 119.097,93.767 119.949,93.767 v1(119.966,93.784) ; v1(162.5,35) 162.6,35 163.75,33.85 R11.1@163.75,33.83 ; R68.1@222.05,27.75 v1(223.25,27.75) ; R87.1@226,47.05 v1(226,48.25)
  Sig 1 w0.25: v1(67.5,37.5) 86.614,37.5 86.914,37.8 112.633,37.8 112.868,38.035 144.111,38.035 144.858,37.288 v1(144.858,37.25) ; v2(136.5,86) 136.595,86 138.095,84.5 138.5,84.5 138.5,84.385 139.635,83.25 143.5,83.25 144.142,82.608 144.142,82.466 v1(144.858,81.75) ; v1(144.858,46.25) 157.5,46.25 158.75,47.5 v1(160,47.5) 219,47.5 220.25,46.25 224,46.25 v1(226,48.25)
  Sig 4 w0.25: v1(66.25,57.5) 66.25,56 68,54.25 68,39.25 67.5,38.75 v1(67.5,37.5) 67.5,35.25 v1(68.25,34.5) ; v1(119.966,93.784) 120.682,94.5 134.5,94.5 136.5,92.5 v2@136.5,86.25 ; v1(144.858,37.25) v1(144.858,46.25) ; v1(144.858,81.75) 144.25,81.142 144.25,46.857 v1(144.858,46.25) ; v1@144.929,46.321 v1(144.858,46.25) ; v1(160,47.5) 160,40 161.25,38.75 161.25,36.25 v1(162.5,35) ; v1(223.25,27.75) 222.25,28.75 222.25,30.5 223.75,32 223.75,44.8 226,47.05 v1(226,48.25)
SDO_HCS05_4: R68.2 U6.15 | length 3.1
  Top Shielding/Sig w0.25: U6.15@217.9,26.475 219.15,26.475 220.425,27.75 R68.2@220.45,27.75
SDO_HCS10_4: R87.2 U7.14 | length 3.6
  Top Shielding/Sig w0.25: R87.2@226,45.45 226,45.425 226.925,44.5 227.5,44.5 227.775,44.225 U7.14@227.775,42.9
SEL0_TPS4HC120_1: R95.2 U17.8 | length 212.5
  Top Shielding/Sig w0.25: v1(113.181,96.5) 113.181,96.431 112.25,95.5 112.25,89.25 112.5,89 U17.8@117.25,89 ; R95.2@194.25,39.3 v1(194.25,40.5)
  Sig 1 w0.25: v1(113.181,96.5) 113.25,96.569 113.25,97.25 114,98 114,100.25 115.5,101.75 v2(151,101.75) ; v2(151.5,19.5) 200.75,19.5 v1(201.25,20)
  Sig 4 w0.25: v2(151,101.75) 151,101.655 151.25,101.405 151.25,100.5 152.75,99 152.75,33.978 151.75,32.978 151.75,19.821 151.5,19.571 v2(151.5,19.5) ; v1(194.25,40.5) 194.25,27 v1(201.25,20)
SEL1_TPS4HC120_1: R96.2 U17.9 | length 161.1
  Top Shielding/Sig w0.25: v1(113.357,98.5) 111.75,96.893 111.75,88.75 111.975,88.525 117.225,88.525 U17.9@117.25,88.5 ; R96.2@196,39.3 v1(196,40.5)
  Sig 1 w0.25: v1(113.357,98.5) 113.431,98.574 113.431,100.431 115.5,102.5 151.5,102.5 154.65,99.35 176.15,99.35 177.683,97.817 177.933,97.817 v2(178,97.75) ; v2(178.5,44.75) 178.554,44.696 193.946,44.696 v1(194,44.643)
  Sig 4 w0.25: v2(178,97.75) 178.061,97.689 178.675,97.689 179,97.364 179,95.75 179,45.25 v2(178.5,44.75) ; v1(194,44.643) 194,44.554 194.25,44.304 194.25,42.25 v1(196,40.5)
SLA_10: Q24.1 Q24.2 Q24.3 R265.2 R281.2 R284.2 U16.40 | length 77
  Top Shielding/Sig w0.2: v1(50.25,61.75) 51,61.75 51.5,61.25 U16.40@56.412,61.25
  Top Shielding/Sig w0.5: v1(8.75,72.75) R284.2@8.75,74.4 ; Q24.1@21.845,71.455 Q24.2@23.115,71.455 Q24.3@24.385,71.455 24.385,70.365 v1(25,69.75) ; v1(48,48) 48.625,48 49.5,48.875 R281.2@49.5,49.95 ; R265.2@49.45,61.75 v1(50.25,61.75)
  Sig 1 w0.5: v1(8.75,72.75) 11.75,69.75 v1(25,69.75) 32.75,69.75 39.5,63 47,63 48.25,61.75 v1(50.25,61.75)
  Sig 4 w0.5: v1(48,48) 48,59.5 v1(50.25,61.75)
SLB_10: Q26.1 Q26.2 Q26.3 R270.2 R282.2 R285.2 U16.41 | length 99.2
  Top Shielding/Sig w0.2: v1(51,60.75) U16.41@56.412,60.75
  Top Shielding/Sig w0.25: v1(55,48) 55.75,48 56.5,48.75 R282.2@56.5,49.95
  Top Shielding/Sig w0.5: v1(3.75,72.75) R285.2@3.75,74.4 ; Q26.1@21.845,53.955 Q26.3@24.385,53.955 24.385,52.865 v1(25,52.25) ; R270.2@43.2,57 43.25,57.05 v1(43.25,58)
  Sig 1 w0.5: v1(43.25,58) 43.25,58.75 45.25,60.75 v1(51,60.75)
  Sig 4 w0.2: v1(51,60.75) 52.5,59.25 52.5,50.5 v1(55,48)
  Sig 4 w0.5: v1(3.75,72.75) 3.75,56.5 8,52.25 v1(25,52.25) 36,52.25 41.75,58 v1(43.25,58)
SLC_10: Q28.1 Q28.2 Q28.3 R277.2 R283.2 R286.2 U16.2 | length 67.9
  Top Shielding/Sig w0.2: v1(56.75,55.75) 57.25,55.75 57.562,56.062 U16.2@57.562,56.6
  Top Shielding/Sig w0.25: R277.2@50.95,44.5 v1(52,44.5) ; v1(62,48) 62.75,48 63.5,48.75 R283.2@63.5,49.95
  Top Shielding/Sig w0.5: R286.2@19.1,35.25 19.1,35.7 19.9,36.5 v1(21,36.5) 21.023,36.478 21.822,36.478 Q28.1@21.845,36.455 Q28.2@23.115,36.455 Q28.3@24.385,36.455
  Sig 1 w0.5: v1(21,36.5) 22,37.5 30,37.5 33.75,41.25 38.75,41.25 42,44.5 v1(52,44.5) 59.5,44.5 62,47 v1(62,48)
  Sig 4 w0.5: v1(56.75,55.75) 57.5,55 57.5,52.5 v1(62,48)
SNA_10: C193.1 C196.2 R287.1 U16.4 | length 12.3
  Top Shielding/Sig w0.2: C193.1@57.033,53.833 57.198,53.998 57.198,54.198 58.562,55.562 U16.4@58.562,56.6
  Top Shielding/Sig w0.25: C196.2@53,51.45 51.35,51.45 R287.1@51.25,51.55 51.279,51.579 51.279,52.279 51.5,52.5 55.7,52.5 C193.1@56.95,53.75 C193.1@57.033,53.833
SNB_10: C194.1 C197.2 R288.1 U16.6 | length 7.4
  Top Shielding/Sig w0.2: C194.1@59.562,53.862 U16.6@59.562,56.6
  Top Shielding/Sig w0.25: C194.1@59.562,53.862 C194.1@59.45,53.75 59.45,52.775 58.25,51.575 R288.1@58.25,51.55 58.35,51.45 C197.2@60,51.45
SNC_10: C195.1 C198.2 R289.1 U16.8 | length 9.6
  Top Shielding/Sig w0.2: U16.8@60.562,56.6 60.562,54.938 61.025,54.475 61.225,54.475 C195.1@61.95,53.75
  Top Shielding/Sig w0.25: C195.1@61.95,53.75 63.2,52.5 64.3,52.5 64.875,51.925 64.9,51.925 65.25,51.575 R289.1@65.25,51.55 65.35,51.45 C198.2@67,51.45
SNS_1HTC30_5: R148.2 R151.2 U11.6 | length 115.1
  Top Shielding/Sig w0.25: R151.2@16,27.95 v1(16,26.75) 17.25,25.5 19.5,25.5 19.925,25.075 19.925,24.075 U11.6@19.95,24.05 ; R148.2@102.25,14.2 102.3,14.25 v1(104,14.25)
  Sig 1 w0.25: v1(16,26.75) 15,25.75 15,21.25 17.5,18.75 25.25,18.75 27.25,16.75 50.75,16.75 60,7.5 102.5,7.5 104,9 v1(104,14.25)
SNS_TPS2HCS05_1: C79.1 J18.65 R73.2 U6.3 | length 152.8
  Top Shielding/Sig w0.25: J18.65@97.79,23.495 98.995,23.495 99.55,24.05 C79.1@100.5,24.05 R73.2@102.25,24.05 ; v1(209.75,29.25) 209.75,28.75 210.25,28.25 210.25,27.5 210.625,27.125 U6.3@212.1,27.125
  Sig 1 w0.25: J18.65@97.79,23.495 97.793,23.497 123.497,23.497 124.25,24.25 126.911,24.25 127.161,24.5 v1(127.25,24.5) ; v1(127.5,41.25) 153.75,41.25 155,42.5 161.425,42.5 163.175,44.25 177,44.25 177.25,44 208.25,44 209.75,42.5 v1(209.75,29.25)
  Sig 4 w0.25: v1(127.25,24.5) 127.25,40.911 127.5,41.161 v1(127.5,41.25)
SNS_TPS2HCS10_1: C85.1 J18.66 R85.2 U7.2 | length 163.4
  Top Shielding/Sig w0.25: J18.66@97.79,20.955 99.295,20.955 99.75,20.5 100.45,20.5 C85.1@100.5,20.55 R85.2@102.25,20.55 ; v1(225.75,35.75) 226.75,35.75 227.066,36.066 227.066,37.041 U7.2@227.125,37.1
  Sig 1 w0.25: J18.66@97.79,20.955 125.097,20.955 v6(126.25,22.107) ; v1(126.25,45) 127.5,45 158.75,45 160,46.25 211.25,46.25 221.75,35.75 v1(225.75,35.75)
  Sig 4 w0.25: v6(126.25,22.107) v1(126.25,45)
SNS_TPS4HC120_1: J18.64 R101.2 | length 2.7
  Top Shielding/Sig w0.25: J18.64@97.79,26.035 100.415,26.035 R101.2@100.45,26
SPA_10: C190.2 C193.2 R281.1 U16.3 | length 13.5
  Top Shielding/Sig w0.2: C193.2@55.55,53.75 56.3,54.5 56.75,54.5 58.062,55.812 U16.3@58.062,56.6
  Top Shielding/Sig w0.25: C190.2@47.75,51.45 49.4,51.45 R281.1@49.5,51.55 49.5,52.5 50,53 54.8,53 C193.2@55.55,53.75
SPB_10: C191.2 C194.2 R282.1 U16.5 | length 7.9
  Top Shielding/Sig w0.2: C194.2@58.05,53.75 58.05,54.3 59.062,55.312 U16.5@59.062,56.6
  Top Shielding/Sig w0.25: C191.2@54.75,51.45 56.4,51.45 R282.1@56.5,51.55 56.5,51.575 56.875,51.95 56.9,51.95 58.05,53.1 C194.2@58.05,53.75
SPC_10: C192.2 C195.2 R283.1 U16.7 | length 7.6
  Top Shielding/Sig w0.2: U16.7@60.062,56.6 60.062,54.688 60.467,54.283 60.467,53.833 C195.2@60.55,53.75
  Top Shielding/Sig w0.25: C195.2@60.55,53.75 61.75,52.55 C192.2@61.75,51.45 63.4,51.45 R283.1@63.5,51.55
SRC_U16_2: C125.1 C126.2 Q7.2 Q7.3 Q7.4 Q9.2 Q9.3 Q9.4 Q10.2 Q10.3 Q10.4 Q11.2 Q11.3 Q11.4 Q12.2 Q12.3 Q12.4 R159.1 R160.1 TP51.1 U12.15 | length 41.9
  Top Shielding/Sig w0.25: U12.15@41.9,139.75 43.25,139.75 43.519,140.019 44.019,140.019 C126.2@44.25,140.25 C125.1@46.484,140.25 ; C125.1@46.484,139.75 C125.1@46.484,140.25 ; v1(46.5,141.25) 46.5,140.266 C125.1@46.484,140.25
  Sig 4 w0.25: v1(42,172.75) 41.5,172.75 39.625,170.875 39.625,155.034 46.5,148.159 v1(46.5,141.25)
  other v1: 44,172.75 46,172.75 59.5,172.75 61.5,172.75 63.5,172.75 52.5,173.65 67.608,174.125 67.608,176.125 42,177.25 44,177.25 46,177.25 59.5,177.25 61.5,177.25 63.5,177.25 67.608,178.125
SRC_U18_3: C155.1 C156.2 Q17.2 Q17.3 Q17.4 Q18.2 Q18.3 Q18.4 Q19.2 Q19.3 Q19.4 Q20.2 Q20.3 Q20.4 Q21.2 Q21.3 Q21.4 R220.1 R222.1 TP53.1 U15.15 | length 56
  Top Shielding/Sig w0.25: U15.15@174.4,124.75 175.55,124.75 175.55,124.94 176.11,125.5 C156.2@176.25,125.5 178,125.5 C155.1@178.242,125.258 ; C155.1@178.25,125.25 C155.1@178.242,125.258 ; v1(178.25,126.75) 178.25,125.266 C155.1@178.242,125.258
  Sig 1 w0.25: v1(178.25,126.75) 182.5,131 182.5,135 v1(185,137.5)
  Sig 4 w0.25: v1(185,137.5) 184.5,138 184.5,171 v1(186.5,173)
  other v1: 188.5,173 190.5,173 204,173 206,173 208,173 193,175 195.5,175 197,175 198.75,175 181.859,175.192 192,176.5 181.859,177.192 186.5,177.25 188.5,177.25 190.5,177.25 204,177.25 206,177.25 208,177.25 181.859,179.192
SS_U5_14: C71.1 U5.8 | length 2.5
  Top Shielding/Sig w0.25: C71.1@134.25,140.6 134.25,140.7 135,141.45 U5.8@135,142.8
SW_11: R120.1 R122.1 U9.3 | length 4.9
  Top Shielding/Sig w0.25: U9.3@211.9,83.5 214.4,83.5 R120.1@214.5,83.599 R122.1@216.75,83.599
SW_U4_14: C59.1 L3.1 U4.13 U4.14
SW_U5_14: L5.1 U5.2
TMP-_TPS1214_7: R37.1 U3.18 | length 5.1
  Top Shielding/Sig w0.25: U3.18@51.25,108.1 51.25,107.5 52,106.75 52,105.55 53.55,104 R37.1@53.575,104
TMR_TPS1212_input1_2: C133.1 R190.2 U12.7 | length 5
  Top Shielding/Sig w0.25: R190.2@35.8,135.75 C133.1@35.8,137.5 38.321,137.5 38.75,137.929 U12.7@38.75,138.1
TMR_TPS1212_input2_3: C162.1 R251.2 U15.7 | length 5
  Top Shielding/Sig w0.25: R251.2@169.8,118.75 C162.1@169.8,120.5 170,120.7 170,121.25 171.25,122.5 U15.7@171.25,123.1
TMR_TPS1214_7: C58.1 R44.2 U3.7 | length 3.8
  Top Shielding/Sig w0.25: R44.2@46.55,114.25 C58.1@46.55,112.5 46.575,112.5 46.925,112.15 46.925,112.125 47.8,111.25 U3.7@48.1,111.25
TPLD_LATCH_RST_1: J18.47 U13.1 | length 168.7
  Top Shielding/Sig w0.25: U13.1@35,126.7 35,126.725 35.025,126.75 v1(37.25,126.75)
  Sig 1 w0.25: v1(37.25,126.75) v2@84.5,126.75 ; v2(84.5,19.25) 85.335,18.415 J18.47@95.25,18.415
  Sig 4 w0.25: v2(84.5,19.25) 84.5,34.063 84.892,34.456 84.892,40.099 84.375,40.616 84.375,48.563 84.625,48.813 84.625,126.625 v2@84.5,126.75
  other v2: 84.62,126.63
TPS1HTC30_ADC_1: C112.1 J18.68 R148.1 | length 4.5
  Top Shielding/Sig w0.25: J18.68@97.79,15.875 100.425,15.875 C112.1@100.5,15.8 R148.1@102.25,15.8
TPS1HTC30_EN_1: R142.1 R143.1 U17.20 | length 144.2
  Top Shielding/Sig w0.25: R142.1@25.7,26 25.725,26 27.021,27.296 27.021,27.721 R143.1@27.3,28 v1@28.5,28 ; U17.20@121.65,86.5 122.841,86.5 123.484,85.857 123.538,85.857 123.896,85.5 v1(124,85.5)
  Sig 1 w0.25: v1(28.562,27.993) 30.744,30.175 36.175,30.175 45.5,39.5 v2(63.5,39.5) ; v2(65.014,46.139) 68.375,49.5 v2@99.739,49.5 ; v2(101.25,67) 116.25,67 v1@117.25,68
  Sig 4 w0.25: v2(63.5,39.5) 65,41 v2@65,46 ; v2(100.006,49.625) 100.625,50.244 100.625,66.375 v2(101.25,67) ; v1@117.25,68 118.3,69.05 118.3,79.8 v1(124,85.5)
  other v1: 117.093,68.009
TPS1HTC30_LATCH_1: J13.5 R144.1 | length 128.6
  Top Shielding/Sig w0.25: R144.1@17.75,29.55 v1(17.75,31.25)
  Sig 1 w0.25: v1(17.75,31.25) 17.75,32.5 19,33.75 31.75,33.75 36.75,38.75 41.25,38.75 43.75,41.25 v1(92.5,41.25)
  Sig 4 w0.25: v1(92.5,41.25) 92,41.75 92,83.745 J13.5@95.25,86.995
TPS1HTC30_OUT: C111.1 D59.1 J7.1 R150.2 U11.8 U11.9 U11.10 | length 8.4
  Top Shielding/Sig w0.25: R150.2@13.75,10.3 17.95,10.3 18,10.25 ; v1@19.3,17.05 U11.8@19.3,18.45 ; v1@19.95,17.05 U11.9@19.95,18.45 ; 20.6,17.1 U11.10@20.6,18.45
  other v1: 19,13.107 19,17 20.25,17
TPS482H85_ADC_1: C108.1 J18.42 R133.2 | length 4.6
  Top Shielding/Sig w0.25: R133.2@90.8,31.25 92.55,31.25 C108.1@92.75,31.05 92.815,31.115 J18.42@95.25,31.115
TPS482H85_OUT1: C103.1 D60.1 J6.1 R139.2 U10.1 | length 4.2
  Top Shielding/Sig w0.25: R139.2@37.05,6.25 J6.1@41.21,6.25
  other v2: 41,12.25 42,13.75 41.75,18.75 42.75,18.75
TPS482H85_OUT2: C104.1 D61.1 J6.2 R140.2 U10.2 | length 4.2
  Top Shielding/Sig w0.25: J6.2@46.29,6.25 R140.2@50.45,6.25
  other v2: 46.5,12.25 45.5,13.75 44.75,18.75 46,18.75
UVLO_11: C100.2 R119.2 R120.2 U9.4 | length 8
  Top Shielding/Sig w0.25: U9.4@211.9,84 213.097,84 214.497,85.401 R120.2@214.5,85.401 R119.2@214.5,88.7 ; C100.2@213,88.8 213.1,88.7 R119.2@214.5,88.7
VDD_HCS05_4: C77.1 R63.2 U6.4 | length 7.3
  Top Shielding/Sig w0.35: R63.2@208.3,31 C77.1@208.3,29.25 208.325,29.25 209.538,28.037 209.538,26.962 210.025,26.475 U6.4@212.1,26.475
VDD_HCS10_4: C80.1 R76.2 TP42.1 U7.3 | length 4.6
  Top Shielding/Sig w0.25: R76.2@226,34.3 C80.1@227.75,34.3 227.775,34.325 U7.3@227.775,37.1
VIN_Cobra_14: C60.2 C61.2 C64.1 C65.1 L4.2 R46.2 R48.2 R49.2 U4.11 U4.17 | length 4.3
  Sig 1 w0.5: v1(123.125,166.375) v1(127.375,166.375)
VOUT1_TPS2HCS05: C72.1 D62.1 J10.1 R69.2 U6.7 U6.8 | length 6.7
  Top Shielding/Sig w0.25: R69.2@203.75,9.55 v1(203.75,10.75)
  Sig 1 w0.25: v1(203.75,10.75) 205.375,12.375 v1(208.625,12.375)
  other v1: 211.75,12.375 210.25,13.75 210,22.5 210.75,23 210,23.375
  other v2: 209,20 210.75,23.75
VOUT1_TPS2HCS10: C81.1 D64.1 J11.1 R77.2 U7.6 U7.7 U7.8
  other v2: 233.75,36.25 232,37 235.5,37.25
VOUT2_TPS2HCS05: C78.1 D63.1 J10.2 R70.2 U6.11 U6.12 | length 6.6
  Top Shielding/Sig w0.25: R70.2@226.25,9.55 v1(226.25,10.75)
  Sig 1 w0.25: v1@221.5,12.375 221.525,12.35 224.65,12.35 v1(226.25,10.75)
  other v1: 218.25,12.375 221.375,12.375 219.75,13.75 220,22.5 219.25,23 220,23.375
  other v2: 220.75,20 219.25,23.75
VOUT2_TPS2HCS10: C84.1 D65.1 J11.2 R78.2 U7.9 U7.10 U7.11
  other v2: 235.5,42.75 232,43 233.75,43.75
VOUT_TPS1211: C135.1 C136.1 C141.1 D38.1 Q14.1 Q14.2 Q14.3 Q15.1 Q15.2 Q15.3 R199.2 T9.1 TP57.1 U14.13 | length 37.8
  Top Shielding/Sig w0.25: U14.13@180.95,61.25 182.825,61.25 183.75,60.325 C141.1@183.75,60.3 183.8,60.25 v1(184.625,60.25) ; T9.1@235,60 235.419,60 241.644,53.775 241.644,51.656 242.125,51.175 242.15,51.175 242.5,50.825 R199.2@242.5,50.8
  Sig 1 w0.25: v1(184.625,60.25) 185.625,59.25 192.5,59.25 194.5,61.25 v1(204.5,61.25)
  other v2: 204.5,55.5 204.5,56.75 204.5,58 211,58.75 214,58.75 221.5,59.75 223.5,59.75 221.5,61.5 223.5,61.5 211,61.75 214,61.75 204.5,63.5 221.5,63.5 223.5,63.5 211,64.5 214,64.5 204.5,64.75 225.75,65 204.5,66
  other v3: 227.856,54.285 228.872,54.285 229.888,54.285 242.239,54.285 243.255,54.285 244.271,54.285 245.287,54.285 227.856,55.301 242.239,55.301 243.255,55.301 244.271,55.301 245.287,55.301 227.856,56.317 242.239,56.317 243.255,56.317 244.271,56.317 245.287,56.317 242.239,57.333 243.255,57.333 244.271,57.333 245.287,57.333 242.239,58.349 243.255,58.349 244.271,58.349 245.287,58.349 242.239,59.365 243.255,59.365 244.271,59.365 245.287,59.365 242.239,60.635 243.255,60.635 244.271,60.635 245.287,60.635 242.239,61.651 243.255,61.651 244.271,61.651 245.287,61.651 242.239,62.667 243.255,62.667 244.271,62.667 245.287,62.667 227.856,63.683 242.239,63.683 243.255,63.683 244.271,63.683 245.287,63.683 227.856,64.699 242.239,64.699 243.255,64.699 244.271,64.699 245.287,64.699 227.856,65.715 228.872,65.715 229.888,65.715 242.239,65.715 243.255,65.715 244.271,65.715 245.287,65.715
VOUT_TPS1214: C46.1 C47.1 C51.1 C52.1 C53.1 D6.1 Q1.2 Q1.3 Q1.4 Q2.2 Q2.3 Q2.4 R30.2 T8.1 TP55.1 U3.15 | length 29.2
  Top Shielding/Sig w0.25: R30.2@17.5,94.55 v1(17.5,95.75) ; U3.15@49.75,108.1 49.75,106.675 49.325,106.25 C53.1@49.3,106.25 C52.1@49.3,104.5 49.3,102.534 C51.1@49.266,102.5 v1(50.5,102.5)
  Top Shielding/Sig w0.5: D6.1@21.25,93.46 v1(21.25,95.75)
  PWR w0.25: v1(17.5,95.75) v1(21.25,95.75) ; v1(48.5,100) 50,100 50.5,100.5 v1(50.5,102.5)
  PWR w0.5: T8.1@15,103.75 15.15,103.75 21.25,97.65 v1(21.25,95.75)
  other v1: 34.5,97.5 36.5,97.5 38.5,97.5 44.5,97.5 46.5,97.5 48.5,97.5
  other v2: 30.75,98 24,98.5 32,98.75 25.5,100.5 27.5,100.5 29.5,100.5
  other v3: 4.713,98.035 5.729,98.035 6.745,98.035 7.761,98.035 20.112,98.035 21.128,98.035 22.144,98.035 4.713,99.051 5.729,99.051 6.745,99.051 7.761,99.051 22.144,99.051 4.713,100.067 5.729,100.067 6.745,100.067 7.761,100.067 22.144,100.067 4.713,101.083 5.729,101.083 6.745,101.083 7.761,101.083 4.713,102.099 5.729,102.099 6.745,102.099 7.761,102.099 4.713,103.115 5.729,103.115 6.745,103.115 7.761,103.115 4.713,104.385 5.729,104.385 6.745,104.385 7.761,104.385 4.713,105.401 5.729,105.401 6.745,105.401 7.761,105.401 4.713,106.417 5.729,106.417 6.745,106.417 7.761,106.417 4.713,107.433 5.729,107.433 6.745,107.433 7.761,107.433 22.144,107.433 4.713,108.449 5.729,108.449 6.745,108.449 7.761,108.449 22.144,108.449 4.713,109.465 5.729,109.465 6.745,109.465 7.761,109.465 20.112,109.465 21.128,109.465 22.144,109.465
VS_ORing_1: D32.1 D33.1 D43.1 R166.2 R227.2 TP47.1 TP49.1 | length 157.5
  Top Shielding/Sig w0.75: R166.2@39,148.3 v8(39,150) ; R227.2@173,135.05 v8(173,136.25)
  Sig 1 w0.75: v8(39,150) 36.25,152.75 36.25,157.5 37,158.25 48.75,158.25 50.25,159.75 67.25,159.75 70,162.5 79.75,162.5 93.75,176.5 v8(93.75,192.5) ; v8(156.25,158.75) 173,142 v8(173,136.25)
  Sig 4 w0.75: v8(156.25,158.75) 154.5,160.5 154.5,190.75 v8(156.25,192.5)
  other v1: 126.75,190.75 91.5,191 123.25,191 158.5,191 92.75,192 157.25,192 125,192.5 92.75,193 157.25,193 91.5,194 158.5,194
VS_U17_8: C137.2 R198.2 U14.20 | length 15.1
  Top Shielding/Sig w0.25: C137.2@180.8,66.25 180.95,66.1 U14.20@180.95,64.75
  Top Shielding/Sig w0.5: R198.2@180,79.5 R198.2@180,79.4 180,76.25 180.8,75.45 C137.2@180.8,66.25
VSNS_14: R52.1 R54.2 U4.1 | length 6.3
  Top Shielding/Sig w0.25: U4.1@126.519,169.819 127.319,169.819 127.75,170.25 129,170.25 129.5,170.75 R52.1@130.7,170.75 R54.2@130.7,172.5
WAKE_TPS1212_input1_1: J15.76 R187.2 | length 238.1
  Top Shielding/Sig w0.25: v1(33.25,140.75) R187.2@33.25,142
  Sig 1 w0.25: v1(33.25,140.75) 31.75,139.25 31.75,131 37.75,125 117.5,125 v1(118,124.5) ; v1@108.904,24.929 109.333,24.5 114.5,24.5 115.25,25.25 134.5,25.25 136.25,23.5 J15.76@138.5,23.5 ; v1@111,109.75 112.5,111.25 v1@118,111.25
  Sig 4 w0.25: v1@109,25 109.5,25.5 109.5,85.75 109.75,86 109.75,107.472 110.895,108.617 110.895,109.391 110.787,109.5 v1@110.75,109.5 ; v1@117.954,124.546 118.5,124 118.5,111.75 v1@118,111.25
  other v1: 108.934,24.915 110.787,109.582 118.037,111.332
WAKE_TPS1212_input1_2: C127.1 R186.1 R187.1 U12.5 | length 8.1
  Top Shielding/Sig w0.25: R187.1@31.65,142 31.65,140.8 31.95,140.5 R186.1@32,140.5 ; R186.1@32,140.25 32.841,140.25 33.216,139.875 34.335,139.875 34.725,139.485 34.725,139.425 34.9,139.25 C127.1@35,139.25 U12.5@38,139.25
WAKE_TPS1212_input2_1: J14.11 R248.2 | length 3
  Top Shielding/Sig w0.25: J14.11@141.25,74.25 143.55,74.25 143.625,74.175 143.65,74.175 144,73.825 R248.2@144,73.8
WAKE_TPS1212_input2_3: C157.1 R247.1 R248.1 U15.5 | length 76.2
  Top Shielding/Sig w0.25: R248.1@144,72.2 144.2,72 v1(145.107,72) ; v1(164.5,121.75) C157.1@165.75,121.75 165.865,121.865 165.865,122.365 166.75,123.25 R247.1@167.75,123.25 167.764,123.264 167.764,123.764 168.25,124.25 U15.5@170.6,124.25
  Sig 1 w0.25: v1@145.25,72 146.841,72 v1(149.75,74.909) v1@149.75,74.804 ; v1(149.75,121.5) 149.839,121.5 150.089,121.75 v1(164.5,121.75)
  Sig 4 w0.25: v1(149.75,74.909) v1(149.75,121.5)
WAKE_TPS1214_1: C54.1 J15.72 R41.1 U3.5 | length 203.3
  Top Shielding/Sig w0.25: R41.1@46.5,117.75 v1(47.25,117.75) 48.25,116.75 48.25,114.071 48.396,113.925 48.825,113.925 49,113.75 49,112.75 49.25,112.5 U3.5@49.25,111.9
  Sig 1 w0.25: v1(47.25,117.75) 49.75,117.75 51.25,116.25 72.5,116.25 73.75,117.5 78.625,117.5 79.875,116.25 v1(108.75,116.25) ; v1(109,14.5) 110.165,13.335 J15.72@138.43,13.335
  Sig 4 w0.25: v1(108.75,116.25) 108.75,109.745 108.4,109.395 108.4,102.994 107.908,102.501 107.908,59.047 108,58.954 108,15.5 v1(109,14.5)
